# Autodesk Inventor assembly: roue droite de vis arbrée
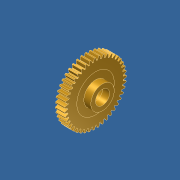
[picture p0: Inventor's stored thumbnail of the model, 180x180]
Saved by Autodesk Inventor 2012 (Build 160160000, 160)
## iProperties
Created: 2011-07
Part Number: roue droite de vis arbrée
Document SubType Name: Assembly
Designer: Laur
Author: Laur
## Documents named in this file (3)
- D:\Formulaire\Sujet CIM 4 Poissy\Modélisation_7970_shimano\roue droite de vis arbrée.iam
- D:\Formulaire\Sujet CIM 4 Poissy\Modélisation_7970_shimano\roue droite sur vis arbrée.ipt
- D:\Formulaire\Sujet CIM 4 Poissy\Modélisation_7970_shimano\roue droite de vis arbrée\Design Accelerator\Engrenages cylindriques2.iam
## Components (2 placed, 2 different names)
1. roue droite sur vis arbrée:1 — coaxialité, Affleurement:1
2. Engrenages cylindriques:1 [sub-assembly] — coaxialité, Affleurement:1
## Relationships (2: Mate 1, Flush 1)
- coaxialité [Mate]: roue droite sur vis arbrée:1 ↔ Engrenages cylindriques:1
- Affleurement:1 [Flush]: roue droite sur vis arbrée:1 ↔ Engrenages cylindriques:1
